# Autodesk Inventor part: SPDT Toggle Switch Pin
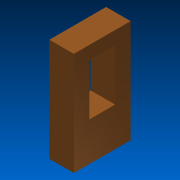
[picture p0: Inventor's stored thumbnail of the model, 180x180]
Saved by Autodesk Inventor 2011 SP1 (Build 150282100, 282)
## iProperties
Created: 2011-11
Part Number: SPDT Toggle Switch Pin
Document SubType Name: Modeling
Designer: sdarley
Density: 1 g/cm^3
Author: sdarley
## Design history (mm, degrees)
sketch "Sketch1"
  geometry: L1 (-0.5, 7)-(-1.725, 7) reference; L2 (-13, 0.5)-(-13, 6.5) reference; L3 (-11.275, 0)-(-12.5, 0) reference; L4 (0, 0.5)-(0, 6.5) reference; L5 (-12, 4.6)-(-11.05, 4.6); L6 (-11.05, 4.6)-(-11.05, 2.4); L7 (-11.05, 2.4)-(-12, 2.4); L8 (-12, 2.4)-(-12, 4.6); L9 (-11.275, 0)-(-11.275, 0.5) reference; L10 (-11.275, 0.5)-(-1.725, 0.5) reference; L11 (-1.725, 0.5)-(-1.725, 0) reference; L12 (-0.5, 0)-(-1.725, 0) reference; L13 (-1.725, 7)-(-1.725, 6.5) reference; L14 (-1.725, 6.5)-(-11.275, 6.5) reference; L15 (-11.275, 6.5)-(-11.275, 7) reference; L16 (-11.275, 7)-(-12.5, 7) reference; A1 r 0.5 centre (-12.5, 6.5) between (-12.5, 7) and (-13, 6.5) reference; A2 r 0.5 centre (-12.5, 0.5) between (-13, 0.5) and (-12.5, 0) reference; A3 r 0.5 centre (-0.5, 0.5) between (-0.5, 0) and (0, 0.5) reference; A4 r 0.5 centre (-0.5, 6.5) between (0, 6.5) and (-0.5, 7) reference; 3 further points
  constraints: 8 end point, 2 midpoint, 2 parallel, 1 horizontal, 1 horizontal alignment, 1 perpendicular
  dimensions: "d0" = 0.95 distance between parallel lines of L6 L8; "d1" = 2.2 distance between parallel lines of L7 L5
extrude "Extrusion1" new body sketch "Sketch1" distance "d2" = 4; taper "d3" = 0 deg
sketch "Sketch2"
  geometry: L1 (-4, 2.2)-(-4, 0) reference; L2 (0, 2.2)-(0, 0) reference; L3 (-3.5, 1.6)-(-1.5, 1.6); L4 (-1.5, 1.6)-(-1.5, 0.6); L5 (-1.5, 0.6)-(-3.5, 0.6); L6 (-3.5, 0.6)-(-3.5, 1.6); 3 further points
  constraints: 8 end point, 2 midpoint, 2 parallel, 1 horizontal, 1 horizontal alignment, 1 perpendicular
  dimensions: "d4" = 1 distance between parallel lines of L5 L3; "d5" = 2 distance between parallel lines of L6 L4; "d6" = 0.5 distance between parallel lines of L1 L6
extrude "Extrusion2" cut sketch "Sketch2" stored distance "d7" = 4; taper "d8" = 0 deg
body "Solid1"
node "Reference1"
